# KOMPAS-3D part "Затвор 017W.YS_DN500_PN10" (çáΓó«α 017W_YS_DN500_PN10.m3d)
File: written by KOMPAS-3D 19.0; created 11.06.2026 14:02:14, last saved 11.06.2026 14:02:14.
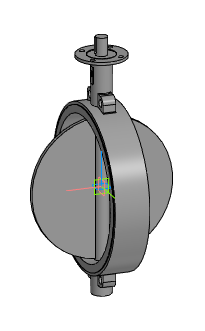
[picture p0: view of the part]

Document properties: Автор: Евгений; Полное имя файла: Z:\3.Личные\kachalov\001_3d для проектировщиков\x.x Тип 017W.Y(S) Затвор дисковый поворотный межфланцевый\_stp_Затвор 017W.YS_DN32-DN1200\Затвор 017W_YS_DN500_PN10.m3d

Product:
- Part/product: Затвор 017W.YS_DN500_PN10

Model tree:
1. Операция без истории:1  (labels: Затвор 017W.YS_DN500_PN10)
